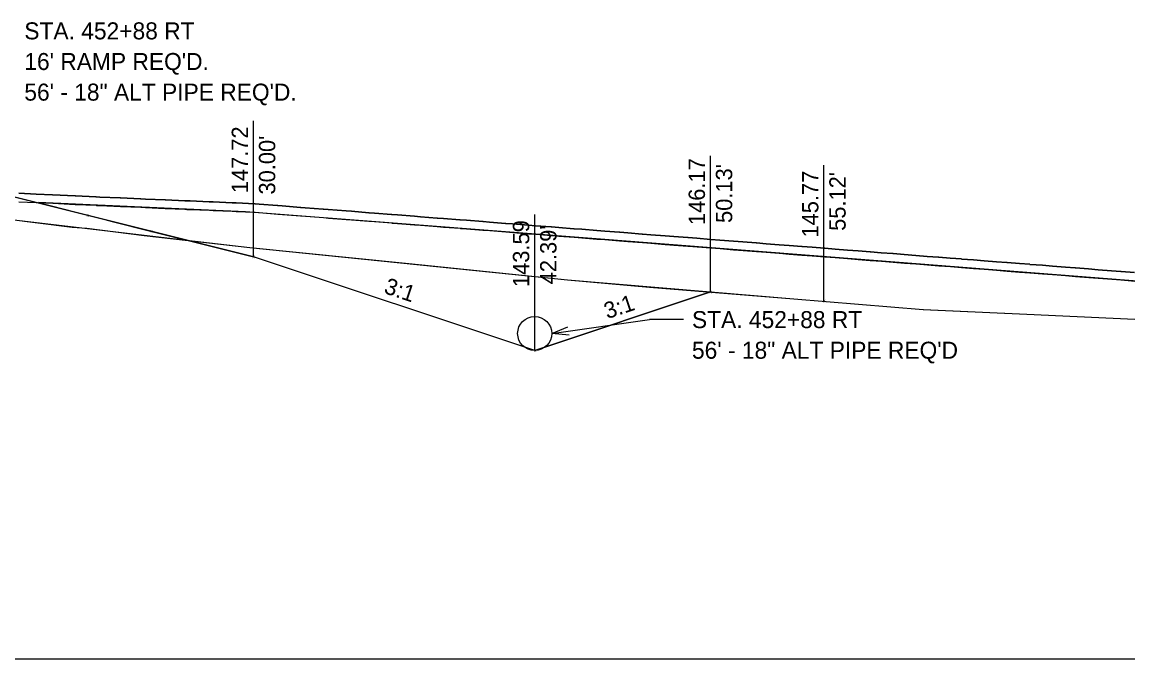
# Model space of a CAD drawing. Extents: x -26 to 4303, y -13 to 10775.
# Drawn here: x 169.81 to 218.51, y 1500 to 1528.07 of the extents above; entities that cross this region are included whole.
import ezdxf

# ---------------------------------------------------------------- set-up
doc = ezdxf.new("R2010")
doc.units = 0
for name, color, linetype in [('CONST_DCH', 7, 'Continuous'), ('CONST_LV3', 7, 'Continuous'), ('DTM_CORRIDOR', 7, 'Continuous'), ('DTM_P_FINISHED_GRADE', 7, 'Continuous'), ('DTM_X_GROUND', 7, 'Continuous'), ('SLOPE_STAKES_FILL', 7, 'Continuous'), ('X_PROFILES_1', 7, 'Continuous'), ('XS_CELL', 7, 'Continuous'), ('XS_P_DR_GRAVEL', 7, 'Continuous'), ('XS_P_DRAINAGE', 7, 'Continuous'), ('XS_P_GROUND', 7, 'Continuous'), ('XS_P_TX_CLEARZONE', 7, 'Continuous'), ('XS_P_TX_FS_BS', 7, 'Continuous'), ('XS_SHEET_EW_TX_AREA', 7, 'Continuous')]:
    doc.layers.add(name, color=color, linetype=linetype)

msp = doc.modelspace()

# ---------------------------------------------------------------- linework, layer by layer
at = {"layer": 'CONST_LV3'}
msp.add_lwpolyline([(173.72, 1519.289), (180, 1517.719)], dxfattribs=at)
at = {"layer": 'DTM_P_FINISHED_GRADE'}
for p, q in [((169.666, 1520.52), (170.422, 1520.488)), ((170.422, 1520.488), (170.433, 1520.488)), ((170.433, 1520.488), (171.15, 1520.458)), ((171.15, 1520.458), (172.14, 1520.405)), ((172.14, 1520.405), (172.154, 1520.404)), ((172.154, 1520.404), (173.063, 1520.365)), ((173.063, 1520.365), (173.077, 1520.365)), ((173.077, 1520.365), (173.234, 1520.356)), ((173.234, 1520.356), (174.133, 1520.317)), ((174.133, 1520.317), (174.147, 1520.316)), ((174.147, 1520.316), (175.027, 1520.278)), ((175.027, 1520.278), (175.04, 1520.278)), ((175.04, 1520.278), (175.237, 1520.268)), ((175.237, 1520.268), (176.109, 1520.23)), ((176.109, 1520.23), (176.122, 1520.229)), ((176.122, 1520.229), (176.975, 1520.192)), ((176.975, 1520.192), (177.049, 1520.189)), ((177.049, 1520.189), (177.063, 1520.188)), ((177.063, 1520.188), (177.207, 1520.182)), ((177.207, 1520.182), (178.053, 1520.145)), ((178.053, 1520.145), (178.066, 1520.145)), ((178.066, 1520.145), (178.222, 1520.138)), ((178.222, 1520.138), (179.057, 1520.102)), ((179.057, 1520.102), (179.07, 1520.101)), ((179.07, 1520.101), (179.237, 1520.094)), ((179.237, 1520.094), (180.061, 1520.058)), ((180.061, 1520.058), (180.074, 1520.057)), ((180.074, 1520.057), (180.251, 1520.044)), ((180.251, 1520.044), (181.065, 1519.98)), ((181.065, 1519.98), (181.077, 1519.979)), ((181.077, 1519.979), (181.266, 1519.964)), ((181.266, 1519.964), (182.069, 1519.901)), ((182.069, 1519.901), (182.081, 1519.901)), ((182.081, 1519.901), (182.281, 1519.885)), ((182.281, 1519.885), (183.072, 1519.823)), ((183.072, 1519.823), (183.085, 1519.822)), ((183.085, 1519.822), (183.295, 1519.806)), ((183.295, 1519.806), (184.076, 1519.744)), ((184.076, 1519.744), (184.088, 1519.744)), ((184.088, 1519.744), (184.31, 1519.726)), ((184.31, 1519.726), (185.08, 1519.666)), ((185.08, 1519.666), (185.092, 1519.665)), ((185.092, 1519.665), (185.325, 1519.647)), ((185.325, 1519.647), (186.084, 1519.587)), ((186.084, 1519.587), (186.095, 1519.587)), ((186.095, 1519.587), (186.34, 1519.567)), ((186.34, 1519.567), (187.088, 1519.509)), ((187.088, 1519.509), (187.099, 1519.508)), ((187.099, 1519.508), (187.355, 1519.488)), ((187.355, 1519.488), (188.091, 1519.43)), ((188.091, 1519.43), (188.103, 1519.43)), ((188.103, 1519.43), (188.369, 1519.409)), ((188.369, 1519.409), (189.095, 1519.352)), ((189.095, 1519.352), (189.106, 1519.351)), ((189.106, 1519.351), (189.384, 1519.329)), ((189.384, 1519.329), (190.099, 1519.273)), ((190.099, 1519.273), (190.11, 1519.273)), ((190.11, 1519.273), (190.399, 1519.25)), ((190.399, 1519.25), (191.103, 1519.195)), ((191.103, 1519.195), (191.114, 1519.194)), ((191.114, 1519.194), (191.413, 1519.171)), ((191.413, 1519.171), (192.107, 1519.116)), ((192.107, 1519.116), (192.117, 1519.116)), ((192.117, 1519.116), (192.428, 1519.091)), ((192.428, 1519.091), (193.111, 1519.038)), ((193.111, 1519.038), (193.121, 1519.037)), ((193.121, 1519.037), (193.443, 1519.012)), ((193.443, 1519.012), (194.114, 1518.959)), ((194.114, 1518.959), (194.125, 1518.959)), ((194.125, 1518.959), (194.458, 1518.933)), ((194.458, 1518.933), (195.118, 1518.881)), ((195.118, 1518.881), (195.128, 1518.88)), ((195.128, 1518.88), (195.472, 1518.853)), ((195.472, 1518.853), (196.122, 1518.802)), ((196.122, 1518.802), (196.132, 1518.802)), ((196.132, 1518.802), (196.487, 1518.774)), ((196.487, 1518.774), (197.126, 1518.724)), ((197.126, 1518.724), (197.136, 1518.723)), ((197.136, 1518.723), (197.502, 1518.695)), ((197.502, 1518.695), (198.13, 1518.645)), ((198.13, 1518.645), (198.139, 1518.645)), ((198.139, 1518.645), (198.517, 1518.615)), ((198.517, 1518.615), (199.133, 1518.567)), ((199.133, 1518.567), (199.143, 1518.566)), ((199.143, 1518.566), (199.531, 1518.536)), ((199.531, 1518.536), (200.137, 1518.488)), ((200.137, 1518.488), (200.147, 1518.488)), ((200.147, 1518.488), (200.546, 1518.457)), ((200.546, 1518.457), (201.141, 1518.41)), ((201.141, 1518.41), (201.15, 1518.409)), ((201.15, 1518.409), (201.561, 1518.377)), ((201.561, 1518.377), (202.145, 1518.331)), ((202.145, 1518.331), (202.154, 1518.331)), ((202.154, 1518.331), (202.576, 1518.298)), ((202.576, 1518.298), (203.149, 1518.253)), ((203.149, 1518.253), (203.158, 1518.252)), ((203.158, 1518.252), (203.59, 1518.218)), ((203.59, 1518.218), (204.153, 1518.174)), ((204.153, 1518.174), (204.161, 1518.174)), ((204.161, 1518.174), (204.605, 1518.139)), ((204.605, 1518.139), (205.156, 1518.096)), ((205.156, 1518.096), (205.165, 1518.095)), ((205.165, 1518.095), (205.62, 1518.06)), ((205.62, 1518.06), (206.16, 1518.017)), ((206.16, 1518.017), (206.169, 1518.017)), ((206.169, 1518.017), (206.635, 1517.98)), ((206.635, 1517.98), (207.164, 1517.939)), ((207.164, 1517.939), (207.172, 1517.938)), ((207.172, 1517.938), (207.649, 1517.901)), ((207.649, 1517.901), (208.168, 1517.86)), ((208.168, 1517.86), (208.176, 1517.86)), ((208.176, 1517.86), (208.664, 1517.822)), ((208.664, 1517.822), (209.172, 1517.782)), ((209.172, 1517.782), (209.179, 1517.781)), ((209.179, 1517.781), (209.679, 1517.742)), ((209.679, 1517.742), (210.176, 1517.703)), ((210.176, 1517.703), (210.183, 1517.703)), ((210.183, 1517.703), (210.694, 1517.663)), ((210.694, 1517.663), (211.179, 1517.625)), ((211.179, 1517.625), (211.187, 1517.624)), ((211.187, 1517.624), (211.708, 1517.584)), ((211.708, 1517.584), (212.183, 1517.546)), ((212.183, 1517.546), (212.19, 1517.546)), ((212.19, 1517.546), (212.723, 1517.504)), ((212.723, 1517.504), (213.187, 1517.468)), ((213.187, 1517.468), (213.194, 1517.467)), ((213.194, 1517.467), (213.738, 1517.425)), ((213.738, 1517.425), (214.191, 1517.39)), ((214.191, 1517.39), (214.198, 1517.389)), ((214.198, 1517.389), (214.753, 1517.346)), ((214.753, 1517.346), (215.195, 1517.311)), ((215.195, 1517.311), (215.201, 1517.31)), ((215.201, 1517.31), (215.767, 1517.266)), ((215.767, 1517.266), (216.198, 1517.232)), ((216.198, 1517.232), (216.205, 1517.232)), ((216.205, 1517.232), (216.782, 1517.187)), ((216.782, 1517.187), (217.202, 1517.154)), ((217.202, 1517.154), (217.209, 1517.153)), ((217.209, 1517.153), (217.797, 1517.107)), ((217.797, 1517.107), (218.206, 1517.075)), ((218.206, 1517.075), (218.212, 1517.075)), ((218.212, 1517.075), (218.812, 1517.028))]:
    msp.add_line(p, q, dxfattribs=at)
at = {"layer": 'DTM_X_GROUND'}
msp.add_lwpolyline([(132.267, 1519.899), (135.382, 1520.433), (138.594, 1520.546), (146.412, 1520.868), (147.073, 1520.864), (150.015, 1520.869), (150.039, 1520.869), (158.801, 1520.858), (159.17, 1520.825), (160.722, 1520.52), (161.768, 1520.323), (172.007, 1519.023), (172.659, 1518.99), (175.189, 1518.664), (179.846, 1518.137), (193.83, 1516.708), (197.437, 1516.386), (203.804, 1515.876), (209.501, 1515.398), (209.508, 1515.398), (214.069, 1515.192), (233.709, 1514.282)], dxfattribs=at)
at = {"layer": 'XS_CELL'}
msp.add_line((150, 1500), (300, 1500), dxfattribs=at)
at = {"layer": 'XS_P_DR_GRAVEL'}
for p, q in [((170.422, 1520.488), (169.666, 1520.52)), ((169.671, 1520.145), (170.427, 1520.113)), ((170.433, 1520.488), (170.422, 1520.488)), ((170.427, 1520.113), (170.438, 1520.113)), ((171.15, 1520.458), (170.433, 1520.488)), ((170.438, 1520.113), (171.155, 1520.083)), ((172.14, 1520.405), (171.15, 1520.458)), ((172.154, 1520.404), (172.14, 1520.405)), ((173.063, 1520.365), (172.154, 1520.404)), ((173.077, 1520.365), (173.063, 1520.365)), ((173.234, 1520.356), (173.077, 1520.365)), ((174.133, 1520.317), (173.234, 1520.356)), ((174.147, 1520.316), (174.133, 1520.317)), ((175.027, 1520.278), (174.147, 1520.316)), ((175.04, 1520.278), (175.027, 1520.278)), ((175.237, 1520.268), (175.04, 1520.278)), ((176.109, 1520.23), (175.237, 1520.268)), ((176.122, 1520.229), (176.109, 1520.23)), ((176.975, 1520.192), (176.122, 1520.229)), ((177.049, 1520.189), (176.975, 1520.192)), ((177.063, 1520.188), (177.049, 1520.189)), ((177.207, 1520.182), (177.063, 1520.188)), ((178.053, 1520.145), (177.207, 1520.182)), ((178.066, 1520.145), (178.053, 1520.145)), ((178.222, 1520.138), (178.066, 1520.145)), ((179.057, 1520.102), (178.222, 1520.138)), ((171.157, 1520.083), (172.147, 1520.03)), ((172.145, 1520.03), (172.16, 1520.029)), ((172.16, 1520.029), (173.068, 1519.99)), ((173.068, 1519.99), (173.082, 1519.989)), ((173.084, 1519.989), (173.241, 1519.98)), ((173.24, 1519.98), (174.139, 1519.942)), ((174.139, 1519.942), (174.152, 1519.941)), ((174.152, 1519.941), (175.032, 1519.903)), ((175.032, 1519.903), (175.046, 1519.902)), ((175.047, 1519.902), (175.243, 1519.892)), ((175.242, 1519.892), (176.114, 1519.855)), ((176.114, 1519.855), (176.128, 1519.854)), ((176.128, 1519.854), (176.981, 1519.817)), ((176.981, 1519.817), (177.055, 1519.814)), ((177.055, 1519.814), (177.068, 1519.813)), ((177.068, 1519.813), (177.212, 1519.807)), ((177.212, 1519.807), (178.059, 1519.77)), ((178.059, 1519.77), (178.072, 1519.77)), ((178.072, 1519.77), (178.227, 1519.763)), ((178.227, 1519.763), (179.063, 1519.727)), ((179.07, 1520.101), (179.057, 1520.102)), ((179.063, 1519.727), (179.075, 1519.726)), ((179.237, 1520.094), (179.07, 1520.101)), ((179.075, 1519.726), (179.242, 1519.719)), ((180.061, 1520.058), (179.237, 1520.094)), ((179.242, 1519.719), (180.066, 1519.683)), ((180.074, 1520.057), (180.061, 1520.058)), ((180.066, 1519.683), (180.079, 1519.682)), ((180.251, 1520.044), (180.074, 1520.057)), ((180.079, 1519.682), (180.257, 1519.668)), ((181.065, 1519.98), (180.251, 1520.044)), ((180.257, 1519.668), (181.07, 1519.605)), ((181.077, 1519.979), (181.065, 1519.98)), ((181.266, 1519.964), (181.077, 1519.979)), ((182.069, 1519.901), (181.266, 1519.964)), ((182.081, 1519.901), (182.069, 1519.901)), ((182.281, 1519.885), (182.081, 1519.901)), ((183.072, 1519.823), (182.281, 1519.885)), ((183.085, 1519.822), (183.072, 1519.823)), ((183.295, 1519.806), (183.085, 1519.822)), ((184.076, 1519.744), (183.295, 1519.806)), ((184.088, 1519.744), (184.076, 1519.744)), ((184.31, 1519.726), (184.088, 1519.744)), ((185.08, 1519.666), (184.31, 1519.726)), ((185.092, 1519.665), (185.08, 1519.666)), ((185.325, 1519.647), (185.092, 1519.665)), ((186.084, 1519.587), (185.325, 1519.647)), ((181.07, 1519.605), (181.083, 1519.604)), ((181.083, 1519.604), (181.271, 1519.589)), ((181.271, 1519.589), (182.074, 1519.526)), ((182.074, 1519.526), (182.086, 1519.525)), ((182.086, 1519.525), (182.286, 1519.51)), ((182.286, 1519.51), (183.078, 1519.448)), ((183.078, 1519.448), (183.09, 1519.447)), ((183.09, 1519.447), (183.301, 1519.43)), ((183.301, 1519.43), (184.082, 1519.369)), ((184.082, 1519.369), (184.094, 1519.368)), ((184.094, 1519.368), (184.316, 1519.351)), ((184.316, 1519.351), (185.085, 1519.291)), ((185.085, 1519.291), (185.097, 1519.29)), ((185.097, 1519.29), (185.33, 1519.272)), ((185.33, 1519.272), (186.089, 1519.212)), ((186.095, 1519.587), (186.084, 1519.587)), ((186.089, 1519.212), (186.101, 1519.211)), ((186.34, 1519.567), (186.095, 1519.587)), ((186.101, 1519.211), (186.345, 1519.192)), ((187.088, 1519.509), (186.34, 1519.567)), ((186.345, 1519.192), (187.093, 1519.134)), ((187.099, 1519.508), (187.088, 1519.509)), ((187.355, 1519.488), (187.099, 1519.508)), ((188.091, 1519.43), (187.355, 1519.488)), ((188.103, 1519.43), (188.091, 1519.43)), ((188.369, 1519.409), (188.103, 1519.43)), ((189.095, 1519.352), (188.369, 1519.409)), ((189.106, 1519.351), (189.095, 1519.352)), ((189.384, 1519.329), (189.106, 1519.351)), ((190.099, 1519.273), (189.384, 1519.329)), ((190.11, 1519.273), (190.099, 1519.273)), ((190.399, 1519.25), (190.11, 1519.273)), ((191.103, 1519.195), (190.399, 1519.25)), ((191.114, 1519.194), (191.103, 1519.195)), ((191.413, 1519.171), (191.114, 1519.194)), ((192.107, 1519.116), (191.413, 1519.171)), ((187.093, 1519.134), (187.105, 1519.133)), ((187.105, 1519.133), (187.36, 1519.113)), ((187.36, 1519.113), (188.097, 1519.055)), ((188.097, 1519.055), (188.108, 1519.054)), ((188.108, 1519.054), (188.375, 1519.034)), ((188.375, 1519.034), (189.101, 1518.977)), ((189.101, 1518.977), (189.112, 1518.976)), ((189.112, 1518.976), (189.389, 1518.954)), ((189.389, 1518.954), (190.105, 1518.898)), ((190.105, 1518.898), (190.116, 1518.898)), ((190.116, 1518.898), (190.404, 1518.875)), ((190.404, 1518.875), (191.108, 1518.82)), ((191.108, 1518.82), (191.119, 1518.819)), ((191.119, 1518.819), (191.419, 1518.796)), ((191.419, 1518.796), (192.112, 1518.741)), ((192.117, 1519.116), (192.107, 1519.116)), ((192.112, 1518.741), (192.123, 1518.741)), ((192.428, 1519.091), (192.117, 1519.116)), ((192.123, 1518.741), (192.434, 1518.716)), ((193.111, 1519.038), (192.428, 1519.091)), ((192.434, 1518.716), (193.116, 1518.663)), ((193.121, 1519.037), (193.111, 1519.038)), ((193.116, 1518.663), (193.126, 1518.662)), ((193.443, 1519.012), (193.121, 1519.037)), ((193.126, 1518.662), (193.448, 1518.637)), ((194.114, 1518.959), (193.443, 1519.012)), ((194.125, 1518.959), (194.114, 1518.959)), ((194.458, 1518.933), (194.125, 1518.959)), ((195.118, 1518.881), (194.458, 1518.933)), ((195.128, 1518.88), (195.118, 1518.881)), ((195.472, 1518.853), (195.128, 1518.88)), ((196.122, 1518.802), (195.472, 1518.853)), ((196.132, 1518.802), (196.122, 1518.802)), ((196.487, 1518.774), (196.132, 1518.802)), ((197.126, 1518.724), (196.487, 1518.774)), ((197.136, 1518.723), (197.126, 1518.724)), ((197.502, 1518.695), (197.136, 1518.723)), ((198.13, 1518.645), (197.502, 1518.695)), ((193.448, 1518.637), (194.12, 1518.584)), ((194.12, 1518.584), (194.13, 1518.584)), ((194.13, 1518.584), (194.463, 1518.558)), ((194.463, 1518.558), (195.124, 1518.506)), ((195.124, 1518.506), (195.134, 1518.505)), ((195.134, 1518.505), (195.478, 1518.478)), ((195.478, 1518.478), (196.127, 1518.427)), ((196.127, 1518.427), (196.137, 1518.427)), ((196.137, 1518.427), (196.493, 1518.399)), ((196.493, 1518.399), (197.131, 1518.349)), ((197.131, 1518.349), (197.141, 1518.348)), ((197.141, 1518.348), (197.507, 1518.319)), ((197.507, 1518.319), (198.135, 1518.27)), ((198.139, 1518.645), (198.13, 1518.645)), ((198.135, 1518.27), (198.145, 1518.27)), ((198.517, 1518.615), (198.139, 1518.645)), ((198.145, 1518.27), (198.522, 1518.24)), ((199.133, 1518.567), (198.517, 1518.615)), ((198.522, 1518.24), (199.139, 1518.192)), ((199.143, 1518.566), (199.133, 1518.567)), ((199.139, 1518.192), (199.148, 1518.191)), ((199.531, 1518.536), (199.143, 1518.566)), ((199.148, 1518.191), (199.537, 1518.161)), ((200.137, 1518.488), (199.531, 1518.536)), ((200.147, 1518.488), (200.137, 1518.488)), ((200.546, 1518.457), (200.147, 1518.488)), ((201.141, 1518.41), (200.546, 1518.457)), ((201.15, 1518.409), (201.141, 1518.41)), ((201.561, 1518.377), (201.15, 1518.409)), ((202.145, 1518.331), (201.561, 1518.377)), ((202.154, 1518.331), (202.145, 1518.331)), ((202.576, 1518.298), (202.154, 1518.331)), ((203.149, 1518.253), (202.576, 1518.298)), ((203.158, 1518.252), (203.149, 1518.253)), ((203.59, 1518.218), (203.158, 1518.252)), ((204.153, 1518.174), (203.59, 1518.218)), ((204.161, 1518.174), (204.153, 1518.174)), ((204.605, 1518.139), (204.161, 1518.174)), ((199.537, 1518.161), (200.143, 1518.113)), ((200.143, 1518.113), (200.152, 1518.113)), ((200.152, 1518.113), (200.552, 1518.081)), ((200.552, 1518.081), (201.147, 1518.035)), ((201.147, 1518.035), (201.156, 1518.034)), ((201.156, 1518.034), (201.566, 1518.002)), ((201.566, 1518.002), (202.15, 1517.956)), ((202.15, 1517.956), (202.159, 1517.956)), ((202.159, 1517.956), (202.581, 1517.923)), ((202.581, 1517.923), (203.154, 1517.878)), ((203.154, 1517.878), (203.163, 1517.877)), ((203.163, 1517.877), (203.596, 1517.843)), ((203.596, 1517.843), (204.158, 1517.799)), ((204.158, 1517.799), (204.167, 1517.799)), ((204.167, 1517.799), (204.611, 1517.764)), ((205.156, 1518.096), (204.605, 1518.139)), ((204.611, 1517.764), (205.162, 1517.721)), ((205.165, 1518.095), (205.156, 1518.096)), ((205.162, 1517.721), (205.17, 1517.72)), ((205.62, 1518.06), (205.165, 1518.095)), ((205.17, 1517.72), (205.625, 1517.685)), ((206.16, 1518.017), (205.62, 1518.06)), ((205.625, 1517.685), (206.166, 1517.642)), ((206.169, 1518.017), (206.16, 1518.017)), ((206.635, 1517.98), (206.169, 1518.017)), ((207.164, 1517.939), (206.635, 1517.98)), ((207.172, 1517.938), (207.164, 1517.939)), ((207.649, 1517.901), (207.172, 1517.938)), ((208.168, 1517.86), (207.649, 1517.901)), ((208.176, 1517.86), (208.168, 1517.86)), ((208.664, 1517.822), (208.176, 1517.86)), ((209.172, 1517.782), (208.664, 1517.822)), ((209.179, 1517.781), (209.172, 1517.782)), ((209.679, 1517.742), (209.179, 1517.781)), ((210.176, 1517.703), (209.679, 1517.742)), ((210.183, 1517.703), (210.176, 1517.703)), ((210.694, 1517.663), (210.183, 1517.703)), ((206.166, 1517.642), (206.174, 1517.642)), ((206.174, 1517.642), (206.64, 1517.605)), ((206.64, 1517.605), (207.169, 1517.564)), ((207.169, 1517.564), (207.178, 1517.563)), ((207.178, 1517.563), (207.655, 1517.526)), ((207.655, 1517.526), (208.173, 1517.485)), ((208.173, 1517.485), (208.181, 1517.485)), ((208.181, 1517.485), (208.67, 1517.447)), ((208.67, 1517.447), (209.177, 1517.407)), ((209.177, 1517.407), (209.185, 1517.406)), ((209.185, 1517.406), (209.684, 1517.367)), ((209.684, 1517.367), (210.181, 1517.328)), ((210.181, 1517.328), (210.189, 1517.328)), ((210.189, 1517.328), (210.699, 1517.288)), ((211.179, 1517.625), (210.694, 1517.663)), ((210.699, 1517.288), (211.185, 1517.25)), ((211.187, 1517.624), (211.179, 1517.625)), ((211.185, 1517.25), (211.192, 1517.249)), ((211.708, 1517.584), (211.187, 1517.624)), ((211.192, 1517.249), (211.714, 1517.209)), ((212.183, 1517.546), (211.708, 1517.584)), ((211.714, 1517.209), (212.189, 1517.171)), ((212.19, 1517.546), (212.183, 1517.546)), ((212.723, 1517.504), (212.19, 1517.546)), ((213.187, 1517.468), (212.723, 1517.504)), ((213.194, 1517.467), (213.187, 1517.468)), ((213.738, 1517.425), (213.194, 1517.467)), ((214.191, 1517.39), (213.738, 1517.425)), ((214.198, 1517.389), (214.191, 1517.39)), ((214.753, 1517.346), (214.198, 1517.389)), ((215.195, 1517.311), (214.753, 1517.346)), ((215.201, 1517.31), (215.195, 1517.311)), ((215.767, 1517.266), (215.201, 1517.31)), ((216.198, 1517.232), (215.767, 1517.266)), ((216.205, 1517.232), (216.198, 1517.232)), ((216.782, 1517.187), (216.205, 1517.232)), ((212.189, 1517.171), (212.196, 1517.171)), ((212.196, 1517.171), (212.729, 1517.129)), ((212.729, 1517.129), (213.192, 1517.093)), ((213.192, 1517.093), (213.199, 1517.092)), ((213.199, 1517.092), (213.743, 1517.05)), ((213.743, 1517.05), (214.196, 1517.014)), ((214.196, 1517.014), (214.203, 1517.014)), ((214.203, 1517.014), (214.758, 1516.97)), ((214.758, 1516.97), (215.2, 1516.936)), ((215.2, 1516.936), (215.207, 1516.935)), ((215.207, 1516.935), (215.773, 1516.891)), ((215.773, 1516.891), (216.204, 1516.857)), ((216.204, 1516.857), (216.21, 1516.857)), ((216.21, 1516.857), (216.788, 1516.812)), ((217.202, 1517.154), (216.782, 1517.187)), ((216.788, 1516.812), (217.208, 1516.779)), ((217.209, 1517.153), (217.202, 1517.154)), ((217.208, 1516.779), (217.214, 1516.778)), ((217.797, 1517.107), (217.209, 1517.153)), ((217.214, 1516.778), (217.802, 1516.732)), ((218.206, 1517.075), (217.797, 1517.107)), ((217.802, 1516.732), (218.211, 1516.7)), ((218.212, 1517.075), (218.206, 1517.075)), ((218.812, 1517.028), (218.212, 1517.075)), ((218.211, 1516.7), (218.218, 1516.7)), ((218.218, 1516.7), (218.817, 1516.653))]:
    msp.add_line(p, q, dxfattribs=at)
at = {"layer": 'XS_P_DRAINAGE'}
for p in [(193.136, 1514.34), (198.939, 1514.954)]:
    msp.add_line(p, (197.439, 1514.954), dxfattribs=at)
msp.add_lwpolyline([(193.905, 1514.261), (193.136, 1514.34), (193.852, 1514.632)], dxfattribs=at)
msp.add_circle((192.386, 1514.34), 0.75, dxfattribs=at)
at = {"layer": 'XS_P_GROUND'}
for points in [[(192.386, 1513.59), (192.386, 1513.59), (180, 1517.719), (168.595, 1520.57)], [(192.386, 1513.59), (200.127, 1516.171)]]:
    msp.add_lwpolyline(points, dxfattribs=at)
at = {"layer": 'XS_P_TX_CLEARZONE'}
for p, q in [((180, 1517.719), (180, 1523.719)), ((180, 1517.719), (180, 1523.719)), ((200.127, 1516.171), (200.127, 1522.171)), ((200.127, 1516.171), (200.127, 1522.171)), ((200.127, 1516.171), (200.127, 1522.171)), ((205.123, 1515.766), (205.123, 1521.766)), ((205.123, 1515.766), (205.123, 1521.766)), ((205.123, 1515.766), (205.123, 1521.766)), ((192.386, 1513.59), (192.386, 1519.59)), ((192.386, 1513.59), (192.386, 1519.59)), ((192.386, 1513.59), (192.386, 1519.59))]:
    msp.add_line(p, q, dxfattribs=at)
at = {"layer": 'XS_SHEET_EW_TX_AREA'}
for points in [[(164, 1520.587), (164, 1520.15), (165.995, 1520.109), (166, 1519.443), (169.2, 1519.378), (177.059, 1518.453), (172.687, 1519.547), (168.925, 1520.488)], [(170.525, 1520.108), (174.873, 1519), (177.053, 1518.46), (179.846, 1518.137), (186.838, 1517.423), (193.83, 1516.708), (200.127, 1516.171), (203.804, 1515.876), (209.501, 1515.398), (214.069, 1515.192), (223.889, 1514.737), (233.709, 1514.282), (245.883, 1513.954), (247.772, 1513.966), (254.06, 1513.902), (235.674, 1515.335), (221.545, 1516.44), (209.185, 1517.406), (195.478, 1518.478), (186.719, 1519.163), (179.654, 1519.701)], [(200.127, 1516.171), (192.386, 1513.59), (180, 1517.719), (177.053, 1518.46), (179.846, 1518.137), (186.838, 1517.423), (193.83, 1516.708)]]:
    msp.add_lwpolyline(points, close=True, dxfattribs=at)

# ---------------------------------------------------------------- texts
at = {"layer": 'CONST_DCH'}
msp.add_text('X', height=0.12, dxfattribs=at).set_placement((192.347, 1513.53))
msp.add_text('X', height=0.12, dxfattribs=at).set_placement((192.347, 1513.53))
at = {"layer": 'DTM_CORRIDOR'}
msp.add_text('X', height=0.12, dxfattribs=at).set_placement((200.088, 1516.111))
at = {"layer": 'SLOPE_STAKES_FILL'}
msp.add_text('X', height=0.12, dxfattribs=at).set_placement((179.961, 1517.659))
at = {"layer": 'X_PROFILES_1'}
for p in [(172.648, 1519.487), (175.461, 1518.784), (205.083, 1515.706)]:
    msp.add_text('X', height=0.12, dxfattribs=at).set_placement(p)
at = {"layer": 'XS_P_DRAINAGE'}
for s, p in [('STA. 452+88 RT', (169.906, 1527.304)), ("16' RAMP REQ'D.", (169.906, 1525.954)), ('56\' - 18" ALT PIPE REQ\'D.', (169.906, 1524.604)), ('STA. 452+88 RT', (199.314, 1514.579)), ('56\' - 18" ALT PIPE REQ\'D', (199.314, 1513.229))]:
    msp.add_text(s, height=0.75, dxfattribs=at).set_placement(p)
at = {"layer": 'XS_P_TX_CLEARZONE'}
for s, p in [('147.72', (179.76, 1520.523)), ('147.72', (179.76, 1520.523)), ("30.00'", (180.96, 1520.466)), ("30.00'", (180.96, 1520.466)), ('146.17', (199.887, 1519.122)), ('146.17', (199.887, 1519.122)), ('146.17', (199.887, 1519.122)), ("50.13'", (201.087, 1519.213)), ("50.13'", (201.087, 1519.213)), ("50.13'", (201.087, 1519.213)), ('145.77', (204.883, 1518.57)), ('145.77', (204.883, 1518.57)), ('145.77', (204.883, 1518.57)), ("55.12'", (206.083, 1518.865)), ("55.12'", (206.083, 1518.865)), ("55.12'", (206.083, 1518.865)), ('143.59', (192.146, 1516.389)), ('143.59', (192.146, 1516.389)), ('143.59', (192.146, 1516.389)), ("42.39'", (193.346, 1516.508)), ("42.39'", (193.346, 1516.508)), ("42.39'", (193.346, 1516.508))]:
    msp.add_text(s, height=0.72, rotation=90, dxfattribs=at).set_placement(p)
at = {"layer": 'XS_P_TX_FS_BS'}
for rotation, p in [(341.5668, (185.707, 1516.133)), (18.4349, (195.581, 1514.972))]:
    msp.add_text('3:1', height=0.72, rotation=rotation, dxfattribs=at).set_placement(p)

doc.saveas('drawing.dxf')
